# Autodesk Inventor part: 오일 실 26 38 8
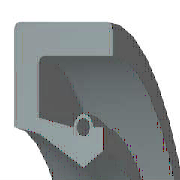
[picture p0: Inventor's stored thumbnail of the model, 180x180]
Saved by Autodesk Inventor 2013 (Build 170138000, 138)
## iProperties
IsCustomPart: 1
Created: 2012-02
Part Number: 오일 실 26 38 8
Material: 고무
Description: 오일-실
Document SubType Name: Modeling
Standard: KS B 2804
Designer: mduedu
Standards Organization: KS
Language: ko-KR
Size Designation: S - 26 38 8
Categories: <MemberInstance><Categories><Category DisplayName="샤프트 부품" InternalName="7f7aeb1f-a693-4053-b835-cee3144e0d98" Mnemonic="SHFT"><Category DisplayName="실링" Intern
Density: 0.93 g/cm^3
Author: mduedu
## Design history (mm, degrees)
revolve "본체" stored, may be unused: angle "d17" = 90 deg
revolve "스프링1" stored, may be unused: angle "d18" = 90 deg
body "Solid1"
sketch "스케치1"
  geometry: L1 (0, 19)-(8, 19); L2 (8, 19)-(8, 17.75); L3 (8, 17.75)-(1.75, 17.75); L4 (0, 19)-(0, 15.1); L5 (0, 15.1)-(1.75, 14.75); L6 (1.75, 14.75)-(4.9, 13); L7 (4.9, 13)-(0, 13); L8 (6.3, 13.875)-(6.3, 15.1); L9 (0, 0)-(9.586, 0) reference; L10 (4.9, 13)-(6.3, 13.875); L11 (0, 18)-(0, -3) reference; L12 (-1.917, 0)-(11.503, 0) reference; L13 (4.2, 15.1)-(1.75, 15.59); L14 (1.75, 15.59)-(1.75, 17.75); L15 (6.3, 15.1)-(5.6, 15.1); C1 r 0.455 at (4.9, 15.1); A1 r 0.7 centre (4.9, 15.1) between (5.6, 15.1) and (4.2, 15.1)
  constraints: 26 end point, 5 horizontal alignment, 4 perpendicular, 2 centre point, 2 collinear, 2 horizontal, 2 parallel, 2 point on circle, 2 point on line, 2 vertical alignment, 1 coincident
  dimensions: "d0" = 38 diameter of L1 L9 (= SD2); "d1" = 27.75 diameter of L8.start L9 (= ABDM); "d2" = 1.25 distance of L1.end L2.end (computed from SD); "d3" = 0.91 diameter of C1 (= SPDI); "d4" = 1.4 diameter of A1 (= SPDA); "d5" = 26 diameter of L6.end L9 (= NND); "d6" = 29.5 diameter of L5.end L9 (= TKDM); "d7" = 30.2 diameter of L4.end L9 (= HLDM); "d8" = 4.9 distance from line of C1.centre L4 (= SPDST); "d9" = 6.3 distance between parallel lines of L8 L4 (= SDI); "d10" = 8 distance between parallel lines of L2 L4 (= SWDT); "d12" = 1.75 distance between parallel lines of L14 L4 (= SD)
fillet "모깎기1" dims "d11" = 0.3 (= RR)
other parameters: "SD2" = 38 [user parameter; used in 1 equation term], "SWDT" = 8 [user parameter; used in 1 equation term], "RR" = 0.3 [user parameter; used in 1 equation term], "SD" = 1.75 [user parameter; used in 2 equation terms], "NND" = 26 [user parameter; used in 1 equation term], "SPDA" = 1.4 [user parameter; used in 1 equation term], "SPDI" = 0.91 [user parameter; used in 1 equation term], "TKDM" = 29.5 [user parameter; used in 1 equation term], "HLDM" = 30.2 [user parameter; used in 1 equation term], "ABDM" = 27.75 [user parameter; used in 1 equation term], "SDI" = 6.3 [user parameter; used in 1 equation term], "SPDST" = 4.9 [user parameter; used in 1 equation term], "d13" = 0, "d14" = 0, "d15" = 0, "LAB" = 0.35 [user parameter]
